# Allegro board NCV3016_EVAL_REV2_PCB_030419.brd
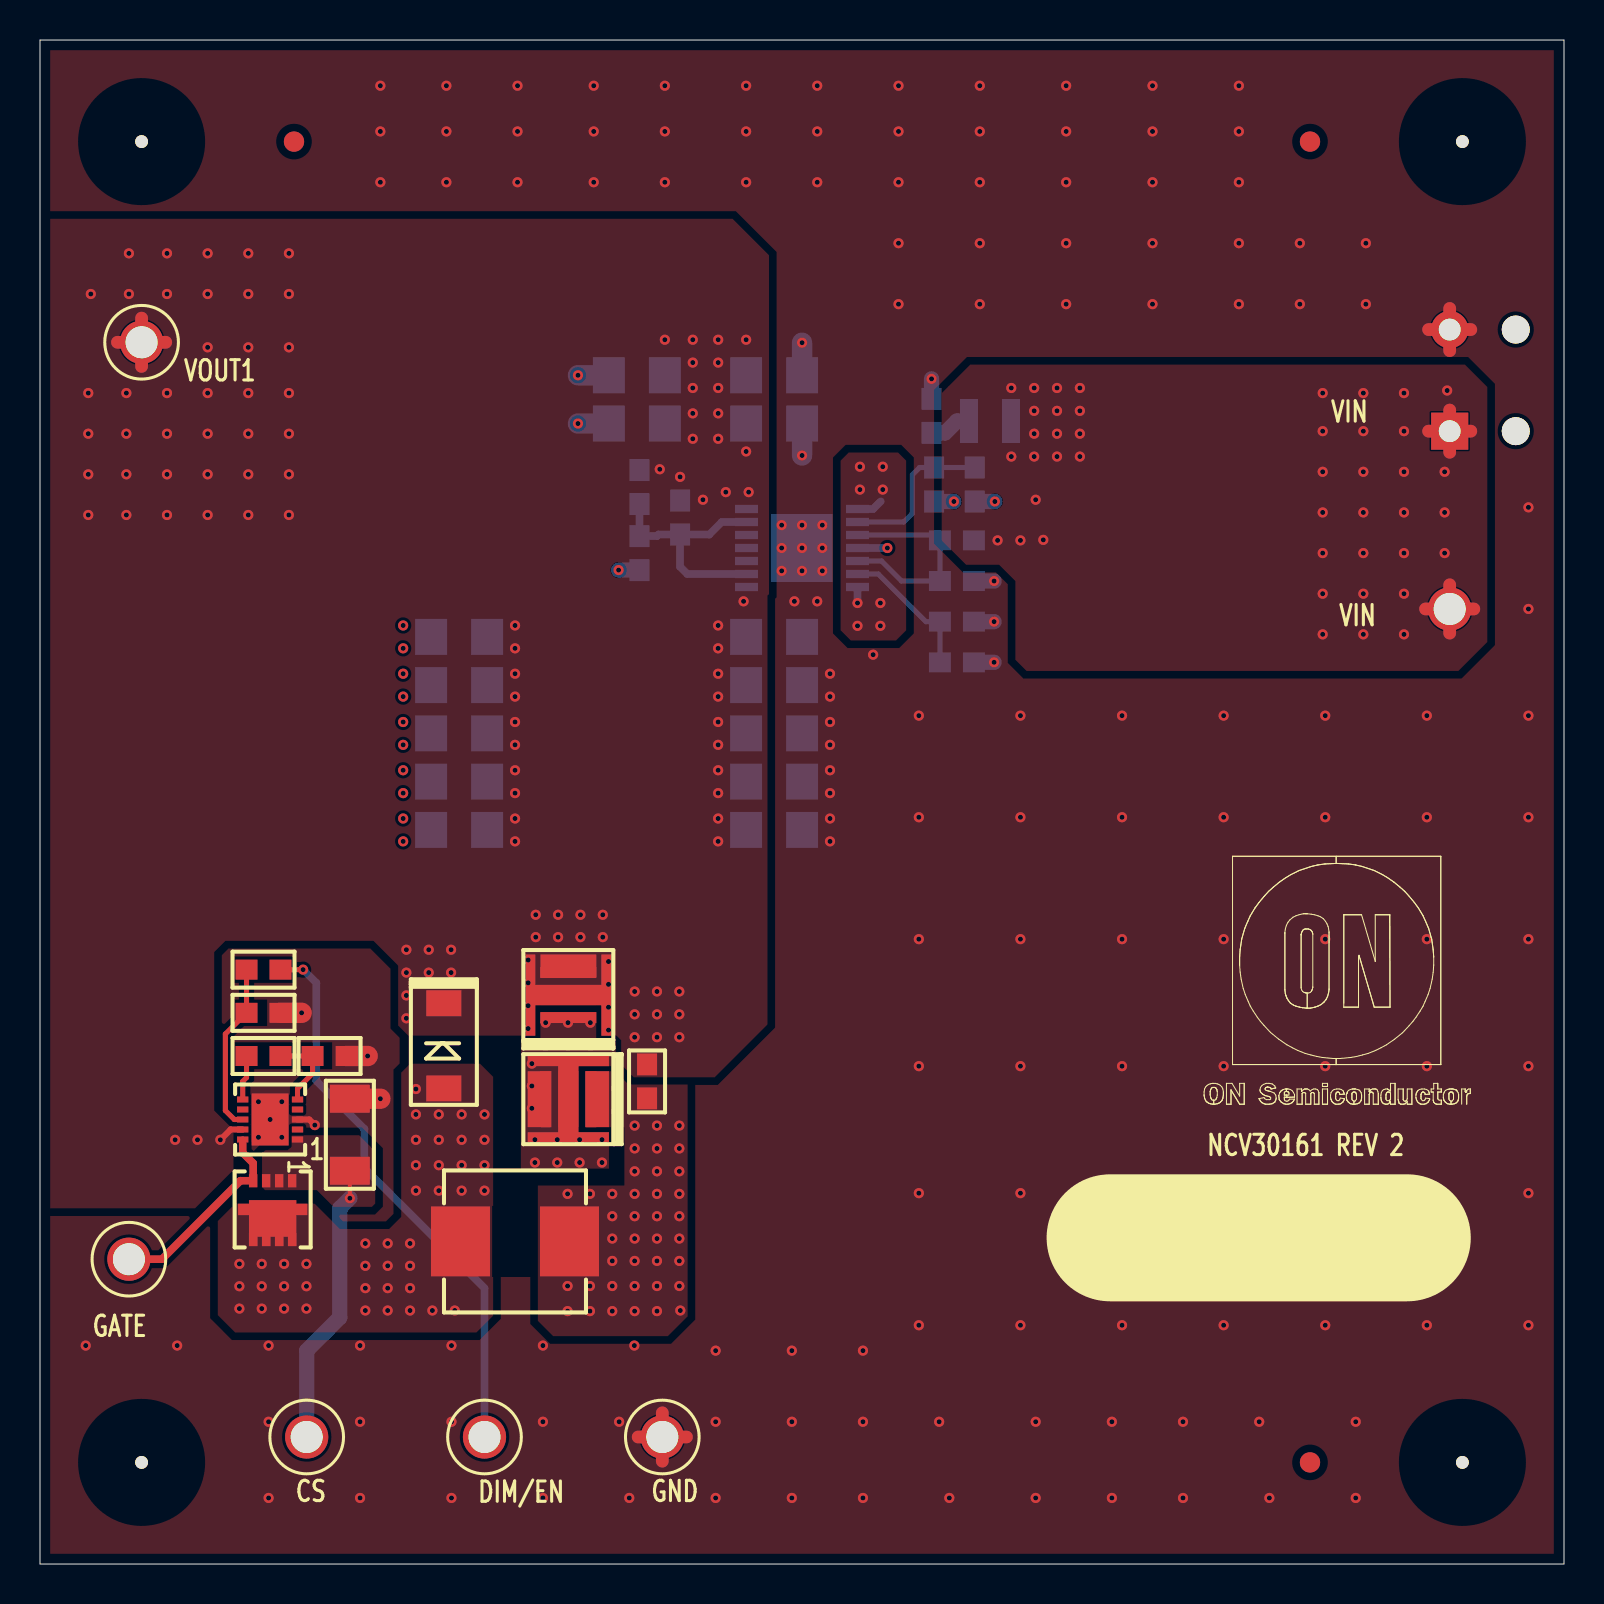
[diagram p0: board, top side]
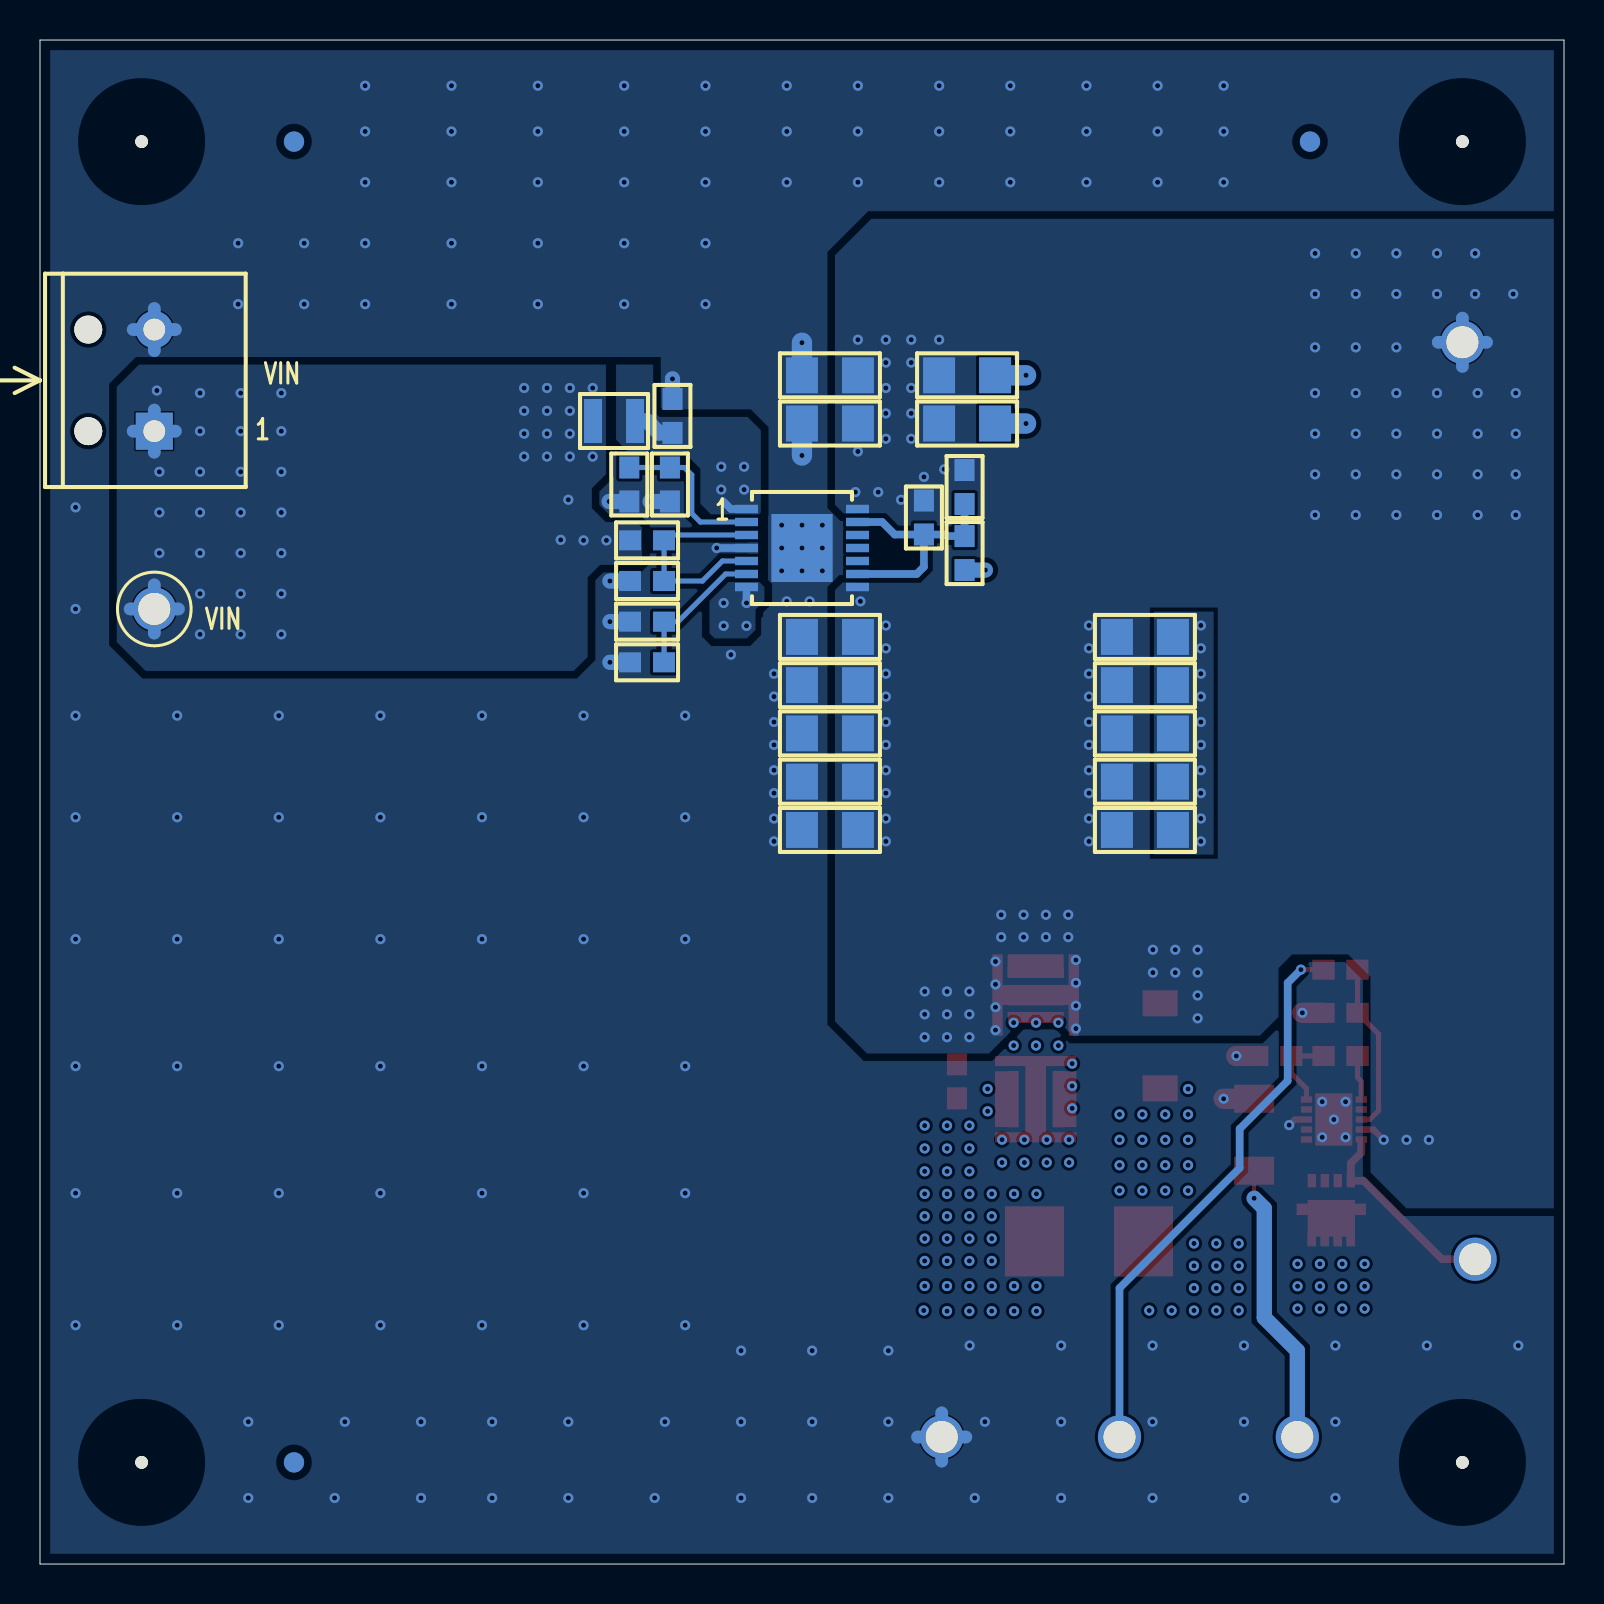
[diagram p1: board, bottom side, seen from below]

Outline 76.2 x 76.2 mm; copper layers: TOP, L02, L03, BOTTOM. Coordinates in mm from the lower left corner of the outline.
Outline path: 0,76.2 0,0 76.2,0 76.2,76.2 0,76.2

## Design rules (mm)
constraint set DEFAULT: min track width 0.2, pair gap 0.2

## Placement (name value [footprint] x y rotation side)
C1  1nF  [0603]  30.35 24.13 90 top
C2  4.7uF  [0603]  14.48 25.4 0 top
C3  22uF  [1206]  29.84 59.44 180 bottom
C4  22uF  [1206]  29.84 57.02 180 bottom
C5  22uF  [1206]  36.7 57.02 0 bottom
C6  22uF  [1206]  36.7 59.44 0 bottom
C7  22uF  [1206]  20.96 43.94 180 bottom
C8  22uF  [1206]  20.96 41.53 180 bottom
C9  22uF  [1206]  20.96 46.36 180 bottom
C10  22uF  [1206]  36.7 46.36 0 bottom
C11  22uF  [1206]  36.7 43.94 0 bottom
C12  22uF  [1206]  36.7 41.53 0 bottom
C13  22uF  [1206]  36.7 39.12 0 bottom
C14  22uF  [1206]  36.7 36.7 0 bottom
C15  22uF  [1206]  20.96 36.7 180 bottom
C16  22uF  [1206]  20.96 39.12 180 bottom
C17  1nF  [0603]  11.18 27.56 0 top
C18  2.2uF  [0603]  44.58 57.4 90 bottom
C19  1.0uF  [0603]  46.74 53.98 270 bottom
C20  1.0uF  [0603]  45.85 45.09 0 bottom
C21  0.1uF  [0603]  29.97 53.85 270 bottom
D1  SFH4725AS  [SMT]  26.42 28.45 270 top
D2  SFH4725AS  [SMT]  26.42 23.24 0 top
D3  -  [NRVTSAF360T3G]  20.19 25.91 90 top
JP1  2PIN/TERM BLK  [TERM_BL_2PS]  70.48 59.18 270 bottom
L1  3.3uH  [74437346033]  23.75 16.13 180 top
L2  10nH  [744762110A]  47.5 57.15 180 bottom
NOREF  -  [unnamed]  71.12 71.12 0 top
NOREF#2  -  [unnamed]  5.08 5.08 0 top
NOREF#3  -  [unnamed]  63.5 71.12 0 top
NOREF#4  -  [unnamed]  5.08 71.12 0 top
NOREF#5  -  [unnamed]  12.7 71.12 0 top
NOREF#6  -  [unnamed]  63.5 5.08 0 top
NOREF#7  -  [unnamed]  71.12 5.08 0 top
NOREF#8  -  [#2]  0 0 0 top
NOREF#9  -  [#2]  0 0 90 top
NOREF#10  -  [unnamed]  12.7 71.12 180 bottom
NOREF#11  -  [unnamed]  63.5 5.08 180 bottom
NOREF#12  -  [unnamed]  63.5 71.12 180 bottom
Q3  NVTFS5C673NL  [WDFN8]  11.63 17.73 0 top
R1  0.2  [SMT_1206]  15.49 21.46 90 top
R2  10K  [0603]  11.18 25.4 180 top
R3  100  [0603]  11.18 29.72 0 top
R4  10K  [0603]  45.85 51.18 180 bottom
R5  10K  [0603]  45.85 49.15 0 bottom
R6  850  [0603]  44.7 53.98 270 bottom
R7  830  [0603]  45.85 47.12 0 bottom
R8  130K  [0603]  32 52.32 270 bottom
R9  10K  [0603]  29.97 50.55 270 bottom
TP1  DIM/EN  [THRU_HOLE]  22.23 6.35 270 top
TP2  CS  [THRU_HOLE]  13.34 6.35 270 top
TP3  GATE  [THRU_HOLE]  4.45 15.24 90 top
TP4  VIN  [THRU_HOLE]  70.48 47.75 180 bottom
TP5  VOUT1  [THRU_HOLE]  5.08 61.09 0 top
TP6  GND  [THRU_HOLE]  31.12 6.35 270 top
U1  NCL30161  [DFN10]  11.51 22.23 180 top
U2  4194  [TSSOP-14]  38.1 50.8 180 bottom

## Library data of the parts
C1-C21 = CAPACITOR
D1 D2 = LED_2
D3 = DIODE
JP1 = CON2_3
L1 L2 = INDUCTOR
Q3 = SO-8_0
R1-R9 = RESISTOR
TP1-TP6 = TEST POINT
U1 = MAX251/SO_2
U2 = 4194_1

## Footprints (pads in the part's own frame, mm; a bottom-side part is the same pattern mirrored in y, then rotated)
0603
  rect 1.1x1.001 smd: 1(-0.85,0) 2(0.85,0)
1206
  rect 1.6x1.8 smd: 1(-1.4,0) 2(1.4,0)
744762110A
  rect 0.9x2.2 smd: 1(-1.05,0) 2(1.05,0)
74437346033
  rect 2.95x3.5 smd: 1(-2.725,0) 2(2.725,0)
DFN10
  rect 0.565x0.3 smd: 1(-1.37,1) 2(-1.37,0.5) 3(-1.37,0) 4(-1.37,-0.5) 5(-1.37,-1) 6(1.37,-1) 7(1.37,-0.5) 8(1.37,0) 9(1.37,0.5) 10(1.37,1)
  rect 1.851x2.602 smd: 11(0,0)
NRVTSAF360T3G
  rect 1.3x1.76 smd: 1(-2.13,0) 2(2.13,0)
SMT
  rect 0.55x2.8 smd: 1(-1.125,0) 2(1.125,0)
  rect 1x2.8 smd: 3(0,0)
SMT_1206
  rect 1.4x2 smd: 1(-1.8,0) 2(1.8,0)
TERM_BL_2PS
  round 1.397 hole 1.397 unplated: (-2.54,-3.302) (2.54,-3.302)
  rect 1.854x1.854 hole 1.092: 1(2.54,0)
  round 1.854 hole 1.092: 2(-2.54,0)
THRU_HOLE
  round 2.159 hole 1.6: 1(0,0)
TSSOP-14
  rect 1.15x0.42 smd: 1(-2.775,1.95) 2(-2.775,1.3) 3(-2.775,0.65) 4(-2.775,0) 5(-2.775,-0.65) 6(-2.775,-1.3) 7(-2.775,-1.95) 8(2.775,-1.95) 9(2.775,-1.3) 10(2.775,-0.65) 11(2.775,0) 12(2.775,0.65) 13(2.775,1.3) 14(2.775,1.95)
  rect 3.06x3.4 smd: 15(0,0)
unnamed
  round 0.635 hole 3.175 unplated: (0,0)
WDFN8
  rect 0.42x0.66 smd: 1(0.975,1.435) 2(0.325,1.435) 3(-0.325,1.435) 4(-0.975,1.435) 5(-0.975,-1.505) 6(-0.325,-1.505) 7(0.325,-1.505) 8(0.975,-1.505)

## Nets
GND_POWER: C2.2 C3.2 C4.2 C5.2 C6.2 C7.2 C8.2 C9.2 C10.2 C11.2 C12.2 C13.2 C14.2 C15.2 C16.2 C17.2 C18.2 C19.2 C20.2 JP1.2 R1.2 R5.2 R6.2 R7.2 R9.2 TP6.1 U1.3 U1.11 U2.4 U2.15
CS: Q3.1 Q3.2 Q3.3(S3) R1.1 TP2.1 U1.1
VOUT1: C1.2 C3.1 C4.1 C5.1 C6.1 C7.1 C8.1 C9.1 C10.1 C11.1 C12.1 C13.1 C14.1 C15.1 C16.1 C21.1 D1.1 D1.3 D3.2(K) R8.1 TP5.1 U1.9(VIN) U2.8(VOUT2) U2.14
N169974: Q3.4 TP3.1 U1.10
N170015: D3.1 L1.2 Q3.5 Q3.6 Q3.7 Q3.8
N170102: D1.2(CATHODE) D2.1 D2.3
N170106: C1.1 D2.2(CATHODE) L1.1
N170654: C2.1 R2.1 U1.5
N170661: R2.2 U1.6
N172599: C17.1 R3.1 U1.8
N172783: R3.2 TP1.1
N173710: R4.2 R5.1 U2.3 U2.5
N173720: C18.1 L2.2 U2.1 U2.7
N174332: C19.1 R6.1 U2.2
N174894: C20.1 R7.1 U2.6
N175528: C21.2 R8.2 R9.1 U2.9 U2.13
N176271: JP1.1 L2.1 R4.1 TP4.1

Pads without a net: U1 2 4 7; U2 10 11 12

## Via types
v1: diameter 0.508, hole 0.254, TOP to BOTTOM, 450 vias

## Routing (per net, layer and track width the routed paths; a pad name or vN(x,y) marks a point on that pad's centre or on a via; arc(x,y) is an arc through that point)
GND_POWER: length 55.7
  TOP w0.305: v1(13.74,21.95) 13.46,22.23 U1.3
  TOP w0.635: 31.12,5.14 TP6.1 ; TP6.1 31.12,7.56 ; TP6.1 29.91,6.35 ; TP6.1 32.32,6.35 ; JP1.2 70.48,62.78 ; JP1.2 69.43,61.72 ; JP1.2 70.48,60.67 ; JP1.2 71.54,61.72
  TOP w1.016: C2.2 v1(16.38,25.4) ; C17.2 v1(13.08,27.56) ; R1.2 v1(17.02,23.26)
  L02 w0.635: JP1.2 71.54,61.72 ; JP1.2 70.48,62.78 ; JP1.2 69.43,61.72 ; JP1.2 70.48,60.67 ; 31.12,5.14 TP6.1 ; TP6.1 31.12,7.56 ; TP6.1 32.32,6.35 ; TP6.1 29.91,6.35
  L03 w0.635: 69.43,61.72 JP1.2 ; JP1.2 71.54,61.72 ; JP1.2 70.48,60.67 ; JP1.2 70.48,62.78 ; 31.12,5.14 TP6.1 ; TP6.1 29.91,6.35 ; TP6.1 31.12,7.56 ; TP6.1 32.32,6.35
  BOTTOM w0.381: U2.4 v1(42.37,50.8)
  BOTTOM w0.635: 29.91,6.35 TP6.1 ; TP6.1 31.12,5.14 ; TP6.1 32.32,6.35 ; TP6.1 31.12,7.56 ; 69.43,61.72 JP1.2 ; JP1.2 71.54,61.72 ; JP1.2 70.48,62.78 ; JP1.2 70.48,60.67
  BOTTOM w0.762: C20.2 v1(47.7,45.09) ; R9.2 v1(28.93,49.7) ; C18.2 v1(44.58,59.26) ; R6.2 v1(45.69,53.13) ; R7.2 v1(47.7,47.12) ; R5.2 v1(47.7,49.15) ; C19.2 v1(47.74,53.13)
  BOTTOM w1.016: C6.2 v1(38.1,61.06) ; C5.2 v1(38.1,55.43) ; C4.2 v1(26.9,57.02) ; C3.2 v1(26.9,59.44)
  vias: v1(2.29,10.92) v1(6.86,10.92) v1(10.92,23.11) v1(10.92,21.34) v1(11.43,10.92) v1(11.43,7.11) v1(11.43,3.3) v1(11.51,22.23) v1(12.09,23.11) v1(12.09,21.34) v1(16,10.92) v1(16,7.11) v1(16,3.3) v1(17.02,73.91) v1(17.02,71.63) v1(17.02,69.09) v1(18.16,46.93) v1(18.16,45.78) v1(18.16,44.51) v1(18.16,43.37) v1(18.16,42.1) v1(18.16,40.96) v1(18.16,39.69) v1(18.16,38.54) v1(18.16,37.27) v1(18.16,36.13) v1(20.32,73.91) v1(20.32,71.63) v1(20.32,69.09) v1(20.57,10.92) v1(20.57,7.11) v1(20.57,3.3) v1(23.88,73.91) v1(23.88,71.63) v1(23.88,69.09) v1(25.15,10.92) v1(25.15,7.11) v1(25.15,3.3) v1(27.69,73.91) v1(27.69,71.63) v1(27.69,69.09) v1(28.96,7.11) v1(29.46,3.3) v1(29.72,10.92) v1(31.24,73.91) v1(31.24,71.63) v1(31.24,69.09) v1(33.78,10.67) v1(33.78,7.11) v1(33.78,3.3) v1(35.31,73.91) v1(35.31,71.63) v1(35.31,69.09) v1(37.08,51.94) v1(37.08,50.8) v1(37.08,49.66) v1(37.59,10.67) v1(37.59,7.11) v1(37.59,3.3) v1(37.72,48.13) v1(38.1,51.94) v1(38.1,50.8) v1(38.1,49.66) v1(38.86,73.91) v1(38.86,71.63) v1(38.86,69.09) v1(38.86,48.13) v1(39.12,51.94) v1(39.12,50.8) v1(39.12,49.66) v1(39.5,44.51) v1(39.5,43.37) v1(39.5,42.1) v1(39.5,40.96) v1(39.5,39.69) v1(39.5,38.54) v1(39.5,37.27) v1(39.5,36.13) v1(41.15,10.67) v1(41.15,7.11) v1(41.15,3.3) v1(41.66,45.47) v1(42.93,73.91) v1(42.93,71.63) v1(42.93,69.09) v1(42.93,66.04) v1(42.93,62.99) v1(43.94,42.42) v1(43.94,37.34) v1(43.94,31.24) v1(43.94,24.89) v1(43.94,18.54) v1(43.94,11.94) v1(44.96,7.11) v1(45.47,3.3) v1(46.99,73.91) v1(46.99,71.63) v1(46.99,69.09) v1(46.99,66.04) v1(46.99,62.99) v1(49.02,42.42) v1(49.02,37.34) v1(49.02,31.24) v1(49.02,24.89) v1(49.02,18.54) v1(49.02,11.94) v1(49.78,7.11) v1(49.78,3.3) v1(51.31,73.91) v1(51.31,71.63) v1(51.31,69.09) v1(51.31,66.04) v1(51.31,62.99) v1(53.59,7.11) v1(53.59,3.3) v1(54.1,42.42) v1(54.1,37.34) v1(54.1,31.24) v1(54.1,24.89) v1(54.1,18.54) v1(54.1,11.94) v1(55.63,73.91) v1(55.63,71.63) v1(55.63,69.09) v1(55.63,66.04) v1(55.63,62.99) v1(57.15,7.11) v1(57.15,3.3) v1(59.18,42.42) v1(59.18,37.34) v1(59.18,31.24) v1(59.18,24.89) v1(59.18,18.54) v1(59.18,11.94) v1(59.94,73.91) v1(59.94,71.63) v1(59.94,69.09) v1(59.94,66.04) v1(59.94,62.99) v1(60.96,7.11) v1(61.47,3.3) v1(62.99,66.04) v1(62.99,62.99) v1(64.26,42.42) v1(64.26,37.34) v1(64.26,31.24) v1(64.26,24.89) v1(64.26,18.54) v1(64.26,11.94) v1(65.79,7.11) v1(65.79,3.3) v1(66.29,66.04) v1(66.29,62.99) v1(69.34,42.42) v1(69.34,37.34) v1(69.34,31.24) v1(69.34,24.89) v1(69.34,18.54) v1(69.34,11.94) v1(74.42,52.83) v1(74.42,47.75) v1(74.42,42.42) v1(74.42,37.34) v1(74.42,31.24) v1(74.42,24.89) v1(74.42,18.54) v1(74.42,11.94)
CS: length 14.2
  TOP w0.2: R1.1 v1(15.49,18.29)
  BOTTOM w0.762: TP2.1 13.34,10.67 14.99,12.32 14.99,17.78 v1(15.49,18.29)
VOUT1: length 15.8
  TOP w0.305: v1(9.02,21.21) 9.53,21.72 U1.9
  TOP w0.635: TP5.1 6.29,61.09 ; TP5.1 5.08,62.29 ; TP5.1 3.87,61.09 ; TP5.1 5.08,59.88
  L02 w0.635: 5.08,59.88 TP5.1 ; TP5.1 3.87,61.09 ; TP5.1 5.08,62.29 ; TP5.1 6.29,61.09
  BOTTOM w0.635: TP5.1 6.29,61.09 ; TP5.1 5.08,62.29 ; TP5.1 5.08,59.88 ; TP5.1 3.87,61.09
  vias: v1(2.41,58.55) v1(2.41,56.52) v1(2.41,54.48) v1(2.41,52.45) v1(2.54,63.5) v1(4.32,58.55) v1(4.32,56.52) v1(4.32,54.48) v1(4.32,52.45) v1(4.45,65.53) v1(4.45,63.5) v1(6.35,65.53) v1(6.35,63.5) v1(6.35,58.55) v1(6.35,56.52) v1(6.35,54.48) v1(6.35,52.45) v1(6.76,21.21) v1(7.87,21.21) v1(8.38,65.53) v1(8.38,63.5) v1(8.38,60.83) v1(8.38,58.55) v1(8.38,56.52) v1(8.38,54.48) v1(8.38,52.45) v1(10.41,65.53) v1(10.41,63.5) v1(10.41,60.83) v1(10.41,58.55) v1(10.41,56.52) v1(10.41,54.48) v1(10.41,52.45) v1(12.45,65.53) v1(12.45,63.5) v1(12.45,60.83) v1(12.45,58.55) v1(12.45,56.52) v1(12.45,54.48) v1(12.45,52.45) v1(18.32,30.71) v1(18.32,29.57) v1(18.32,28.43) v1(18.32,27.28) v1(19.44,30.71) v1(19.44,29.57) v1(20.55,30.71) v1(20.55,29.57) v1(23.75,46.93) v1(23.75,45.78) v1(23.75,44.51) v1(23.75,43.37) v1(23.75,42.1) v1(23.75,40.96) v1(23.75,39.69) v1(23.75,38.54) v1(23.75,37.27) v1(23.75,36.13) v1(24.41,30.2) v1(24.41,29.06) v1(24.41,27.91) v1(24.41,26.77) v1(24.79,32.46) v1(24.79,31.34) v1(25.9,32.46) v1(25.9,31.34) v1(27.02,32.46) v1(27.02,31.34) v1(28.14,32.46) v1(28.14,31.34) v1(28.43,30.12) v1(28.43,28.98) v1(28.43,27.84) v1(28.43,26.7) v1(29.73,28.63) v1(29.73,27.48) v1(29.73,26.34) v1(30.85,28.63) v1(30.85,27.48) v1(30.85,26.34) v1(30.99,54.74) v1(31.24,61.21) v1(32,54.36) v1(31.97,28.63) v1(31.97,27.48) v1(31.97,26.34) v1(32.64,61.21) v1(32.64,60.07) v1(32.64,58.8) v1(32.64,57.53) v1(32.64,56.26) v1(33.15,53.21) v1(33.91,61.21) v1(33.91,60.07) v1(33.91,58.8) v1(33.91,57.53) v1(33.91,56.26) v1(33.91,46.93) v1(33.91,45.78) v1(33.91,44.51) v1(33.91,43.37) v1(33.91,42.1) v1(33.91,40.96) v1(33.91,39.69) v1(33.91,38.54) v1(33.91,37.27) v1(33.91,36.13) v1(34.29,53.59) v1(35.18,48.13) v1(35.31,61.21) v1(35.31,55.63) v1(35.43,53.59)
N169974: length 10.1
  TOP w0.305: U1.10 10.14,21.03
  TOP w0.381: 10.14,21.03 10.14,20.56 10.66,20.04 Q3.4 10.02,19.16 6.1,15.24 TP3.1
N170015:
  vias: v1(9.97,15.01) v1(9.97,13.89) v1(9.97,12.77) v1(11.09,15.01) v1(11.09,13.89) v1(11.09,12.77) v1(12.2,15.01) v1(12.2,13.89) v1(12.2,12.77) v1(13.32,15.01) v1(13.32,13.89) v1(13.32,12.77) v1(16.27,16.03) v1(16.27,14.91) v1(16.27,13.79) v1(16.27,12.67) v1(17.38,16.03) v1(17.38,14.91) v1(17.38,13.79) v1(17.38,12.67) v1(18.5,16.03) v1(18.5,14.91) v1(18.5,13.79) v1(18.5,12.67) v1(18.8,23.75) v1(18.8,22.48) v1(18.8,21.21) v1(18.8,19.94) v1(18.8,18.67) v1(19.62,12.67) v1(19.94,22.48) v1(19.94,21.21) v1(19.94,19.94) v1(19.94,18.67) v1(20.74,12.67) v1(21.08,22.48) v1(21.08,21.21) v1(21.08,19.94) v1(21.08,18.67) v1(22.23,22.48) v1(22.23,21.21) v1(22.23,19.94) v1(22.23,18.67)
N170102:
  vias: v1(24.59,25.02) v1(24.59,23.9) v1(24.59,22.78) v1(24.75,21.22) v1(24.75,20.07) v1(25.28,27.07) v1(25.28,25.92) v1(25.86,21.22) v1(25.86,20.07) v1(26.4,27.07) v1(26.4,25.92) v1(26.98,21.22) v1(26.98,20.07) v1(27.52,27.07) v1(27.52,25.92) v1(28.1,21.22) v1(28.1,20.07)
N170106:
  vias: v1(26.38,18.51) v1(26.38,13.9) v1(26.38,12.64) v1(27.5,18.51) v1(27.5,13.9) v1(27.5,12.64) v1(28.61,18.51) v1(28.61,17.39) v1(28.61,16.27) v1(28.61,15.15) v1(28.61,13.9) v1(28.61,12.64) v1(28.82,23.75) v1(28.82,22.64) v1(29.73,21.92) v1(29.73,20.78) v1(29.73,19.63) v1(29.73,18.51) v1(29.73,17.39) v1(29.73,16.27) v1(29.73,15.15) v1(29.73,13.9) v1(29.73,12.64) v1(30.85,21.92) v1(30.85,20.78) v1(30.85,19.63) v1(30.85,18.51) v1(30.85,17.39) v1(30.85,16.27) v1(30.85,15.15) v1(30.85,13.9) v1(30.85,12.64) v1(31.97,21.92) v1(31.97,20.78) v1(31.97,19.63) v1(31.97,18.51) v1(31.97,17.39) v1(31.97,16.27) v1(31.97,15.15) v1(31.97,13.9) v1(32.01,12.67)
N170654: length 4.1
  TOP w0.254: R2.1 C2.1 13.63,24.52 12.88,23.77 U1.5
N170661: length 2.3
  TOP w0.254: R2.2 10.33,24.32 10.14,24.13 U1.6
N172599: length 8.5
  TOP w0.254: R3.1 C17.1 9.27,26.5 9.27,22.67 9.72,22.23 U1.8
N172783: length 28.3
  TOP w0.254: R3.2 v1(13.15,29.72)
  BOTTOM w0.381: TP1.1 22.23,13.79 16.22,19.8 16.22,21.76 13.82,24.16 13.82,29.06 v1(13.15,29.72)
N173710: length 10.8
  BOTTOM w0.254: U2.5 42.08,50.15 43.08,49.15 R5.1 R4.2 44.73,51.45 U2.3
N173720: length 4.2
  BOTTOM w0.381: 42.04,53.13 41.66,52.75 U2.1 ; U2.7 v1(40.87,48.05)
  BOTTOM w0.762: L2.2 45.85,57.15 45.25,56.55 C18.1
  vias: v1(40.87,46.91) v1(41,54.86) v1(41,53.72) v1(42.02,48.05) v1(42.02,46.91) v1(42.14,54.86) v1(42.14,53.72)
N174332: length 8.1
  BOTTOM w0.254: U2.2 43.18,52.1 43.61,52.53 43.61,54.46 43.98,54.82 R6.1 C19.1
N174894: length 7.1
  BOTTOM w0.254: U2.6 41.91,49.5 44.3,47.12 R7.1 C20.1
N175528: length 12.3
  BOTTOM w0.381: U2.9 32.36,49.5 32,49.86 R8.2 ; R8.2 33.47,51.47 34.09,52.1 U2.13 ; R8.2 30.93,51.47 30.85,51.4 R9.1 C21.2
N176271: length 27.1
  TOP w0.635: 69.28,47.75 TP4.1 ; TP4.1 70.48,48.96 ; TP4.1 70.48,46.54 ; TP4.1 71.69,47.75 ; JP1.1 71.54,56.64 ; JP1.1 70.48,55.59 ; JP1.1 70.48,57.7 ; JP1.1 69.43,56.64
  L02 w0.635: JP1.1 70.48,57.7 ; JP1.1 69.43,56.64 ; JP1.1 71.54,56.64 ; JP1.1 70.48,55.59 ; 70.48,46.54 TP4.1 ; TP4.1 69.28,47.75 ; TP4.1 70.48,48.96 ; TP4.1 71.69,47.75
  BOTTOM w0.635: JP1.1 70.48,57.7 ; JP1.1 70.48,55.59 ; JP1.1 71.54,56.64 ; JP1.1 69.43,56.64 ; 70.48,46.54 TP4.1 ; TP4.1 71.69,47.75 ; TP4.1 69.28,47.75 ; TP4.1 70.48,48.96
  vias: v1(47.88,51.18) v1(48.56,58.8) v1(48.56,55.37) v1(49.02,51.18) v1(49.71,58.8) v1(49.71,57.66) v1(49.71,56.52) v1(49.71,55.37) v1(49.78,53.21) v1(50.16,51.21) v1(50.85,58.8) v1(50.85,57.66) v1(50.85,56.52) v1(50.85,55.37) v1(51.99,58.8) v1(51.99,57.66) v1(51.99,56.52) v1(51.99,55.37) v1(64.14,58.55) v1(64.14,56.64) v1(64.14,54.61) v1(64.14,52.58) v1(64.14,50.55) v1(64.14,48.51) v1(64.14,46.48) v1(66.17,58.55) v1(66.17,56.64) v1(66.17,54.61) v1(66.17,52.58) v1(66.17,50.55) v1(66.17,48.51) v1(66.17,46.48) v1(68.2,58.55) v1(68.2,56.64) v1(68.2,54.61) v1(68.2,52.58) v1(68.2,50.55) v1(68.2,48.51) v1(68.2,46.48) v1(70.23,54.61) v1(70.23,52.58) v1(70.23,50.55) v1(70.36,58.67)

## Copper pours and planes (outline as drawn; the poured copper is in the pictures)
GND_POWER on TOP: 0.51,0.51 0.51,75.69 75.69,75.69 75.69,0.51 ; 4 cut-outs
GND_POWER on BOTTOM: 20.51,47.62 20.51,35.47 17.52,35.47 17.52,47.62
GND_POWER on BOTTOM: 0.51,0.51 0.51,75.69 75.69,75.69 75.69,0.51 ; 2 cut-outs
GND_POWER on BOTTOM: 37.15,47.62 37.15,35.47 40.14,35.47 40.14,47.29 39.82,47.62
GND_POWER on L02, L03: 0.51,0.51 0.51,75.69 75.69,75.69 75.69,0.51
CS on TOP, L02: 14.68,17.86 13.84,18.69 11.25,18.69 11.1,18.85 11.1,20.52 11.26,20.69 12.38,20.69 12.54,20.85 12.54,21.37 12.61,21.44 15.96,21.44 16.76,20.63 16.76,18.02 16.59,17.86
VOUT1 on TOP (solid shape): 27.81,29.34 25.02,29.34 25.02,30.48 27.81,30.48
VOUT1 on TOP (solid shape): 24.77,28.96 28.07,28.96 28.07,30.48 28.58,30.48 28.58,26.42 28.07,26.42 28.07,27.94 24.77,27.94 24.77,26.42 24.26,26.42 24.26,30.48 24.77,30.48
VOUT1 on TOP, L02: 0.51,67.26 34.63,67.26 36.45,65.44 36.45,48.49 36.37,48.42 36.37,26.97 33.73,24.33 29.69,24.33 29.06,24.97 29.06,26.19 28.83,26.42 28.07,26.42 28.07,27.94 24.77,27.94 24.77,26.42 18.42,26.42 17.91,26.92 17.91,29.92 16.67,31.16 9.27,31.16 8.71,30.6 8.71,22.67 9.67,21.71 9.67,19.71 7.75,17.78 0.51,17.78
VOUT1 on BOTTOM: 0.51,17.78 0.51,67.26 34.63,67.26 36.45,65.44 36.45,52.96 36.02,52.53 34.7,52.53 34.7,49.07 36.07,49.07 36.45,48.69 36.45,27.13 34.85,25.53 28.75,25.53 27.17,27.11 25.26,27.11 24.56,26.42 15.21,26.42 14.27,27.36 14.27,29.79 13.59,30.48 10.8,30.48 9.67,29.36 9.67,19.58 7.88,17.78 ; 1 cut-out
N170015 on TOP (solid shape): 12.82,18.01 13.37,18.01 13.37,17.44 12.82,17.44 12.82,15.89 12.4,15.89 12.4,16.36 12.17,16.36 12.17,15.89 11.75,15.89 11.75,16.36 11.52,16.36 11.52,15.89 11.1,15.89 11.1,16.36 10.87,16.36 10.87,15.89 10.45,15.89 10.45,17.44 9.9,17.44 9.9,18.01 10.45,18.01 10.45,18.19 12.82,18.19
N170015 on TOP, L02: 9.76,11.58 21.82,11.58 22.66,12.42 22.66,24.36 22,25.02 18.51,25.02 18.06,24.57 18.06,17.35 17.45,16.75 15,16.75 13.74,18.01 9.76,18.01 8.89,17.15 8.89,12.45
N170102 on TOP (solid shape): 25.53,21.84 24.38,21.84 24.38,24.64 25.53,24.64
N170102 on TOP (solid shape): 28.45,24.89 26.92,24.89 26.92,21.59 28.45,21.59 28.45,21.08 24.38,21.08 24.38,21.59 25.91,21.59 25.91,24.89 24.38,24.89 24.38,25.4 28.45,25.4
N170102 on TOP, L02: 25.02,27.6 27.81,27.6 27.81,26.09 28.79,26.09 28.79,24.89 26.92,24.89 26.92,21.58 28.45,21.58 28.45,19.77 24.04,19.77 24.04,26.17 25.02,26.17
N170106 on TOP (solid shape): 28.45,21.84 27.3,21.84 27.3,24.64 28.45,24.64
N170106 on TOP, L02: 24.89,12.16 24.89,18.92 29.22,18.92 29.22,21.84 27.27,21.84 27.27,24.64 28.76,24.64 29.42,23.98 32.38,23.98 32.38,12.38 31.39,11.39 25.66,11.39
N173720 on TOP, L02: 40.03,46.69 40.03,55.17 40.44,55.58 42.9,55.58 43.31,55.17 43.31,46.69 42.8,46.18 40.54,46.18
N173720 on BOTTOM: 42.65,52.48 40.26,52.48 40.16,52.58 40.16,56.69 40.82,57.35 45.24,57.35 45.54,57.66 45.54,59.97 47.4,59.97 47.4,56.21 46.81,55.63 44.04,55.63 43.18,54.76 43.18,53.01
N173720 on BOTTOM: 40.23,49.1 41.81,49.1 42.72,48.18 42.72,46.53 42.47,46.28 40.85,46.28 40.42,46.71 40.42,47.73 39.98,48.17 39.98,48.84
N176271 on TOP, L02: 46.51,59.97 71.25,59.97 72.36,58.85 72.36,46.1 70.92,44.65 49.33,44.65 48.77,45.21 48.77,49.15 47.96,49.96 46.3,49.96 45.09,51.18 45.09,58.55
N176271 on BOTTOM: 46.38,52.1 47.91,52.1 48.61,52.8 48.61,53.78 47.9,54.49 47.9,59.97 71.25,59.97 72.36,58.85 72.36,46.1 70.92,44.65 49.52,44.65 48.82,45.35 48.82,49.34 48.19,49.96 46.3,49.96 46.1,50.16 46.1,51.82

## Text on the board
BOTTOM: BOTTOM
Ref Des/Assembly Bottom: BOTTOM ASSEMBLY
Board Geometry/Soldermask Bottom: SOLDERMASK_BOTTOM
Package Geometry/Pastemask Bottom: BOTTOM PASTE
Ref Des/Silkscreen Bottom: VIN | SILKSCREEN_BOTTOM
User.Comments: UNLESS OTHERWISE SPECIFIED | DIMENSIONS ARE IN INCHES | TOLERANCES ON; | 2 PL DECIMALS +/- .005 | 3 PL DECIMALS +/- | ANGLES +/- 1.0 DEGREE | FRACTIONS +/- | DRAWN | CHECKED | ENGRG | ISSUED | SIGNATURES | 03/01/19 | DATE | SCALE | SIZE | FSCM NO | DWG NO | SHEET | .015 | USE PURSUANT TO COMPANY INSTRUCTIONS | REV | DESCRIPTION | 1/1 | REVISIONS | APPROVED | ON Semiconductor | D
TOP: TOP
Ref Des/Assembly Top: TOP ASSEMBLY
Board Geometry/Soldermask Top: SOLDERMASK_TOP
Package Geometry/Pastemask Top: TOP PASTE
Ref Des/Silkscreen Top: GATE | VOUT1 | CS | DIM/EN | GND | NCV30161 REV 2 | VIN | TOP SILKSCREEN
L02: LAYER 2 GND
L03: LAYER 3 GND
PAGE_OUTLINE: E | D | C | B | A | 6 | 5 | 4 | 3 | 2 | 1 | ATP-19-018 | LAYERS : | DATE : MAR 2019 | NAME : NCV30161 REV 2 | REV:2
DIMENSION: 2.7 MIL PREPREG (+0.8/-0.7 MILS) | ADJUST TO MEET OVERALL BOARD THICKNESS OF 62 MILS | -.005 | 1 OF 1 | NCV30161 REV 2 | FABRICATION DRAWING | FAB
DEVICE_TYPE_TOP: FIGURE | FINISHED_SIZE | 10.0 | 10.01 | 43.0 | 63.0 | 55.0 | 125.0 | DRILL CHART: TOP to BOTTOM | ALL UNITS ARE IN MILS | TOLERANCE_DRILL | +3.0/-3.0 | +2.0/-0.0 | +2.0/-2.0 | PLATED | NON-PLATED | QTY | 436 | 14 | 2 | 6 | 4
DEVICE_TYPE_BOTTOM: 6. HOLES LESS THAN 12 MIL ARE DRILL SIZES AND NOT FINISHED HOLE SIZES (FHS).OTHER HOLES ARE FINISHED HOLE SIZES | 16.BOW AND TWIST SHOULD NOT EXCEED 0.005" PER INCH. | 17.CLIP SILKSCREEN ON NO MASK AREA. | 14.THIS BOARD MUST BE ROHS COMPLAINT. | 15.REMOVE UNUSED PADS IN ALL INNER LAYERS. | 8. SOLDER MASK COMPONENT SIDE AND SOLDER SIDE WITH LPI SOLDER MASK COLOR GREEN. | 9. IF ANY BGA EXISTS ON THE BOARD, PLUG VIAS FROM THE TOP SIDE WITH SOLDER MASK. | 10. FINISHED THICKNESS TO BE +/- .006" OR 10% WICHEVER IS GREATER. | 11. SILKSCREEN COMPONENT SIDE AND BOTTOM SIDE WITH WHITE NON-CONDUCTIVE EPOXY INK. | 12.BREAK ALL SHARP EDGES. | 13.NO VENDOR LOGO OR NAME ON THE BOARD. | 1. APPLICABLE STANDARDS / SPECIFICATIONS: | ANSI Y14.5-1982, DIMENTIONS AND TOLERANCES. | 2. COMPONENT SIDE SHOWN. | 3. THICKNESS AND MATERIAL: .O62" +/- 0.06"THK.  FR4 | 4. OUTER LAYER TO FINISH AT 1.5OZ COPPER. INNER LAYER 1.5OZ COPPER. | 5. MINIMUM PLATING IN ALL THE THROUGH HOLE SHALL BE 0.001 INCH Cu. | ALL HOLES ARE PLATED THROUGH UNLESS OTHERWISE SPECIFIED. | HOLE SIZE ARE FINISHED SIZE. | 7. PLATING: IMMERSION GOLD | NOTES: (UNLESS OTHERWISE SPECIFIED) | LANDS AND EXPOSED PLATED AREA TO BE FREE OF INK.
